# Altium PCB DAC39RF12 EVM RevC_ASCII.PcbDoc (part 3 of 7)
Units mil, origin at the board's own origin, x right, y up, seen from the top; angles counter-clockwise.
Board outline 5071.81 x 2716.54 mil, 16 copper layers (Top Layer, L2 GND1, L3 PWR1, L4 GND2, L5 PWR2, L6 GND3, L7 Ctrl Signal 1, L8 GND4, L9 GND5, L10 Ctrl Signal 2, L11 GND6, L12 PWR3, L13 GND7, L14 PWR4, L15 GND8, Bottom Layer), stack 82.4 mil thick; 596 components, 375 nets, 3310 pads, 1662 vias.
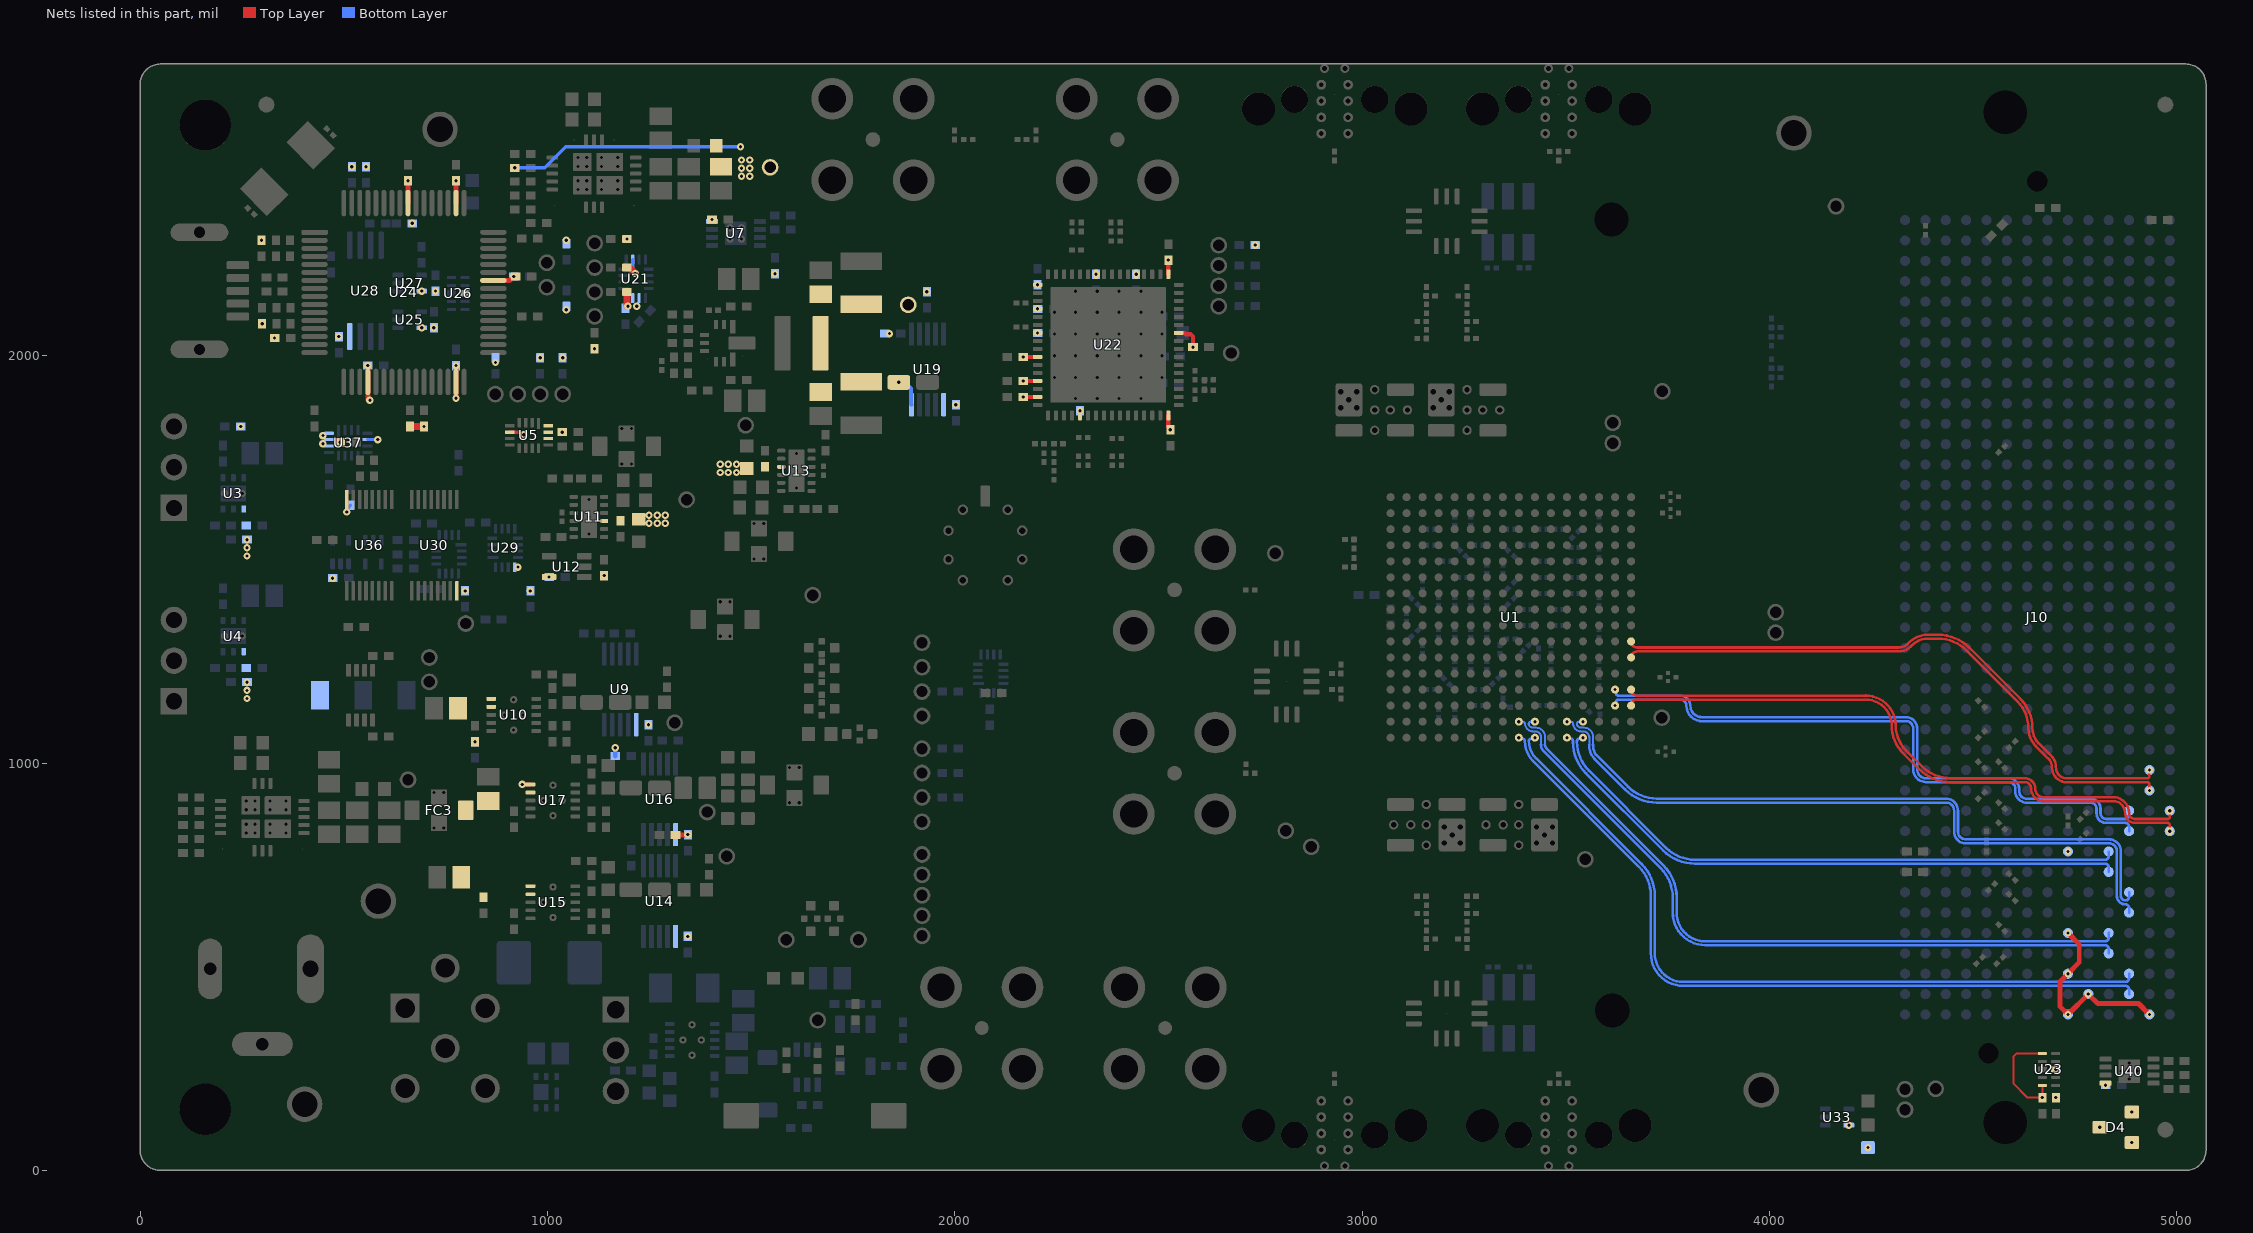
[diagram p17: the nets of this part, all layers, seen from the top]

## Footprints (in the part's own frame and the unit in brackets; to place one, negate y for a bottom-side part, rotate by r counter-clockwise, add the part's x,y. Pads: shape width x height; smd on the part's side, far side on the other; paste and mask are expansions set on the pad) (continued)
NKD0064A [mm] "QFN, 64-Leads, Body 9x9mm, Pitch 0.5mm"
  rrect40% 0.6x0.25 smd mask+0: 1(-4.4,3.75) 2(-4.4,3.25) 3(-4.4,2.75) 4(-4.4,2.25) 5(-4.4,1.75) 6(-4.4,1.25) 7(-4.4,0.75) 8(-4.4,0.25) 9(-4.4,-0.25) 10(-4.4,-0.75) 11(-4.4,-1.25) 12(-4.4,-1.75) 13(-4.4,-2.25) 14(-4.4,-2.75) 15(-4.4,-3.25) 16(-4.4,-3.75) 33(4.4,-3.75) 34(4.4,-3.25) 35(4.4,-2.75) 36(4.4,-2.25) 37(4.4,-1.75) 38(4.4,-1.25) 39(4.4,-0.75) 40(4.4,-0.25) 41(4.4,0.25) 42(4.4,0.75) 43(4.4,1.25) 44(4.4,1.75) 45(4.4,2.25) 46(4.4,2.75) 47(4.4,3.25) 48(4.4,3.75)
  rrect40% 0.25x0.6 smd mask+0: 17(-3.75,-4.4) 18(-3.25,-4.4) 19(-2.75,-4.4) 20(-2.25,-4.4) 21(-1.75,-4.4) 22(-1.25,-4.4) 23(-0.75,-4.4) 24(-0.25,-4.4) 25(0.25,-4.4) 26(0.75,-4.4) 27(1.25,-4.4) 28(1.75,-4.4) 29(2.25,-4.4) 30(2.75,-4.4) 31(3.25,-4.4) 32(3.75,-4.4) 49(3.75,4.4) 50(3.25,4.4) 51(2.75,4.4) 52(2.25,4.4) 53(1.75,4.4) 54(1.25,4.4) 55(0.75,4.4) 56(0.25,4.4) 57(-0.25,4.4) 58(-0.75,4.4) 59(-1.25,4.4) 60(-1.75,4.4) 61(-2.25,4.4) 62(-2.75,4.4) 63(-3.25,4.4) 64(-3.75,4.4)
  round 0.454 hole 0.2 mask+0: 65(-3.35,-2.04) 65(-3.35,-0.68) 65(-3.35,0.68) 65(-3.35,2.04) 65(-2.04,2.04) 65(-2.04,3.35) 65(-2.04,-0.68) 65(-2.04,0.68) 65(-2.04,-3.35) 65(-2.04,-2.04) 65(-0.68,3.35) 65(-0.68,2.04) 65(-0.68,0.68) 65(-0.68,-0.68) 65(-0.68,-2.04) 65(-0.68,-3.35) 65(0.68,3.35) 65(0.68,2.04) 65(0.68,0.68) 65(0.68,-0.68) 65(0.68,-2.04) 65(0.68,-3.35) 65(2.04,2.04) 65(2.04,3.35) 65(2.04,-0.68) 65(2.04,0.68) 65(2.04,-3.35) 65(2.04,-2.04) 65(3.35,-2.04) 65(3.35,-0.68) 65(3.35,0.68) 65(3.35,2.04)
  rrect1% 7.2x7.2 smd paste-3.6 mask+0: 65(0,0)
  silkscreen extent -4.65,-4.65 4.65,4.65
ProbePoint_TH_40mil [mil]
  round 41 hole 28: 1(0,0)
RAPC722X [mm] "Conn_DC Jack"
  oval 1.7x4.3 hole 1.01 slot 3.56 at 90 deg: 1(14.194,0)
  oval 1.5x3.8 hole 0.76 slot 3.05 at 90 deg: 2(7.946,0)
  oval 3.8x1.5 hole 0.76 slot 3.05 at 0 deg: 3(11.197,-4.7)
  silkscreen extent 0.2,-4.57 14.93,4.57
RDU0028A [mm]
  rrect40% 0.7x0.25 smd paste+0 mask+0: 3(-2.1,0.5) 4(-2.1,0) 5(-2.1,-0.5) 15(2.1,-0.5) 16(2.1,0) 17(2.1,0.5)
  rrect40% 0.25x0.7 smd paste+0 mask+0: 8(-1,-2.6) 9(-0.5,-2.6) 10(0,-2.6) 11(0.5,-2.6) 12(1,-2.6) 20(1,2.6) 21(0.5,2.6) 22(0,2.6) 23(-0.5,2.6) 24(-1,2.6)
  round 0.454 hole 0.2 mask+0: 25(-1,1) 25(-1,0.45) 25(-0.45,1) 25(-0.45,0.45) 26(-1,-0.475) 26(-1,-1.475) 26(-0.45,-0.475) 26(-0.45,-1.475) 27(0.45,-0.475) 27(0.45,-1.475) 27(1,-0.475) 27(1,-1.475) 28(0.45,1) 28(0.45,0.45) 28(1,1) 28(1,0.45)
  rrect9% 1.15x1.15 smd paste-1000 mask+0: 25(-0.725,0.725) 28(0.725,0.725)
  rrect9% 1.15x1.65 smd paste-1000 mask+0: 26(-0.725,-0.975) 27(0.725,-0.975)
  round 0.025 smd paste+0 mask+0.05: " "(-2.1,1.25) " "(-2.1,-1.25) " "(-1.987,-2.488) " "(-1.987,2.487) " "(1.987,-2.488) " "(1.988,2.488) " "(2.1,-1.25) " "(2.1,1.25)
  silkscreen extent -3.2,-3.13 2.63,3.13
RPY0014A [mm]
  rrect20% 0.575x0.25 smd paste+0 mask+0: 2(-1.412,0.5) 3(-1.412,0) 4(-1.412,-0.5)
  rrect20% 0.25x0.575 smd paste+0 mask+0: 6(-0.7,-1.162) 7(-0.2,-1.162) 13(-0.2,1.162) 14(-0.7,1.162)
  rrect10% 0.35x0.851 smd paste+0 mask+0: 8(0.35,-1.025) 12(0.35,1.025)
  rrect10% 1.675x0.8 smd paste-0.825 mask+0: 10(0.913,0)
  round 0.025 smd paste+0 mask+0.05: " "(-1.213,0.987) " "(-1.212,-0.988) " "(0.975,-0.8) " "(0.975,0.8)
  silkscreen extent -2.4,-1.63 1.92,1.63
RSV0016A [mm] "QFN, 16-Leads, Body 1.8x2.6mm, Pitch 0.4mm, TI Recommended"
  rrect25% 0.7x0.2 smd mask+0: 1(-0.75,0.6)
  rrect25% 0.6x0.2 smd mask+0: 2(-0.8,0.2) 3(-0.8,-0.2) 4(-0.8,-0.6) 9(0.8,-0.6) 10(0.8,-0.2) 11(0.8,0.2) 12(0.8,0.6)
  rrect25% 0.2x0.6 smd mask+0: 5(-0.6,-1.2) 6(-0.2,-1.2) 7(0.2,-1.2) 8(0.6,-1.2) 13(0.6,1.2) 14(0.2,1.2) 15(-0.2,1.2) 16(-0.6,1.2)
  silkscreen extent -1.08,-1.33 1.08,1.45
Samtec_ASP-184330-01 [mil] "Terminal Array, 1.27mm, 40x14, SMT"
  round 25 smd far side paste-25.2: A1(975,-225) A2(925,-225) A3(875,-225) A4(825,-225) A5(775,-225) A6(725,-225) A7(675,-225) A8(625,-225) A9(575,-225) A10(525,-225) A11(475,-225) A12(425,-225) A13(375,-225) A14(325,-225) A15(275,-225) A16(225,-225) A17(175,-225) A18(125,-225) A19(75,-225) A20(25,-225) A21(-25,-225) A22(-75,-225) A23(-125,-225) A24(-175,-225) A25(-225,-225) A26(-275,-225) A27(-325,-225) A28(-375,-225) A29(-425,-225) A30(-475,-225) A31(-525,-225) A32(-575,-225) A33(-625,-225) A34(-675,-225) A35(-725,-225) A36(-775,-225) A37(-825,-225) A38(-875,-225) A39(-925,-225) A40(-975,-225) B1(975,-175) B2(925,-175) B3(875,-175) B4(825,-175) B5(775,-175) B6(725,-175) B7(675,-175) B8(625,-175) B9(575,-175) B10(525,-175) B11(475,-175) B12(425,-175) B13(375,-175) B14(325,-175) B15(275,-175) B16(225,-175) B17(175,-175) B18(125,-175) B19(75,-175) B20(25,-175) B21(-25,-175) B22(-75,-175) B23(-125,-175) B24(-175,-175) B25(-225,-175) B26(-275,-175) B27(-325,-175) B28(-375,-175) B29(-425,-175) B30(-475,-175) B31(-525,-175) B32(-575,-175) B33(-625,-175) B34(-675,-175) B35(-725,-175) B36(-775,-175) B37(-825,-175) B38(-875,-175) B39(-925,-175) B40(-975,-175) C1(975,-125) C2(925,-125) C3(875,-125) C4(825,-125) C5(775,-125) C6(725,-125) C7(675,-125) C8(625,-125) C9(575,-125) C10(525,-125) C11(475,-125) C12(425,-125) C13(375,-125) C14(325,-125) C15(275,-125) C16(225,-125) C17(175,-125) C18(125,-125) C19(75,-125) C20(25,-125) C21(-25,-125) C22(-75,-125) C23(-125,-125) C24(-175,-125) C25(-225,-125) C26(-275,-125) C27(-325,-125) C28(-375,-125) C29(-425,-125) C30(-475,-125) C31(-525,-125) C32(-575,-125) C33(-625,-125) C34(-675,-125) C35(-725,-125) C36(-775,-125) C37(-825,-125) C38(-875,-125) C39(-925,-125) C40(-975,-125) D1(975,-75) D2(925,-75) D3(875,-75) D4(825,-75) D5(775,-75) D6(725,-75) D7(675,-75) D8(625,-75) D9(575,-75) D10(525,-75) D11(475,-75) D12(425,-75) D13(375,-75) D14(325,-75) D15(275,-75) D16(225,-75) D17(175,-75) D18(125,-75) D19(75,-75) D20(25,-75) D21(-25,-75) D22(-75,-75) D23(-125,-75) D24(-175,-75) D25(-225,-75) D26(-275,-75) D27(-325,-75) D28(-375,-75) D29(-425,-75) D30(-475,-75) D31(-525,-75) D32(-575,-75) D33(-625,-75) D34(-675,-75) D35(-725,-75) D36(-775,-75) D37(-825,-75) D38(-875,-75) D39(-925,-75) D40(-975,-75) E1(975,-25) E2(925,-25) E3(875,-25) E4(825,-25) E5(775,-25) E6(725,-25) E7(675,-25) E8(625,-25) E9(575,-25) E10(525,-25) E11(475,-25) E12(425,-25) E13(375,-25) E14(325,-25) E15(275,-25) E16(225,-25) E17(175,-25) E18(125,-25) E19(75,-25) E20(25,-25) E21(-25,-25) E22(-75,-25) E23(-125,-25) E24(-175,-25) E25(-225,-25) E26(-275,-25) E27(-325,-25) E28(-375,-25) E29(-425,-25) E30(-475,-25) E31(-525,-25) E32(-575,-25) E33(-625,-25) E34(-675,-25) E35(-725,-25) E36(-775,-25) E37(-825,-25) E38(-875,-25) E39(-925,-25) E40(-975,-25) F1(975,25) F2(925,25) F3(875,25) F4(825,25) F5(775,25) F6(725,25) F7(675,25) F8(625,25) F9(575,25) F10(525,25) F11(475,25) F12(425,25) F13(375,25) F14(325,25) F15(275,25) F16(225,25) F17(175,25) F18(125,25) F19(75,25) F20(25,25) F21(-25,25) F22(-75,25) F23(-125,25) F24(-175,25) F25(-225,25) F26(-275,25) F27(-325,25) F28(-375,25) F29(-425,25) F30(-475,25) F31(-525,25) F32(-575,25) F33(-625,25) F34(-675,25) F35(-725,25) F36(-775,25) F37(-825,25) F38(-875,25) F39(-925,25) F40(-975,25) G1(975,75) G2(925,75) G3(875,75) G4(825,75) G5(775,75) G6(725,75) G7(675,75) G8(625,75) G9(575,75) G10(525,75) G11(475,75) G12(425,75) G13(375,75) G14(325,75) G15(275,75) G16(225,75) G17(175,75) G18(125,75) G19(75,75) G20(25,75) G21(-25,75) G22(-75,75) G23(-125,75) G24(-175,75) G25(-225,75) G26(-275,75) G27(-325,75) G28(-375,75) G29(-425,75) G30(-475,75) G31(-525,75) G32(-575,75) G33(-625,75) G34(-675,75) G35(-725,75) G36(-775,75) G37(-825,75) G38(-875,75) G39(-925,75) G40(-975,75) H1(975,125) H2(925,125) H3(875,125) H4(825,125) H5(775,125) H6(725,125) H7(675,125) H8(625,125) H9(575,125) H10(525,125) H11(475,125) H12(425,125) H13(375,125) H14(325,125) H15(275,125) H16(225,125) H17(175,125) H18(125,125) H19(75,125) H20(25,125) H21(-25,125) H22(-75,125) H23(-125,125) H24(-175,125) H25(-225,125) H26(-275,125) H27(-325,125) H28(-375,125) H29(-425,125) H30(-475,125) H31(-525,125) H32(-575,125) H33(-625,125) H34(-675,125) H35(-725,125) H36(-775,125) H37(-825,125) H38(-875,125) H39(-925,125) H40(-975,125) J1(975,175) J2(925,175) J3(875,175) J4(825,175) J5(775,175) J6(725,175) J7(675,175) J8(625,175) J9(575,175) J10(525,175) J11(475,175) J12(425,175) J13(375,175) J14(325,175) J15(275,175) J16(225,175) J17(175,175) J18(125,175) J19(75,175) J20(25,175) J21(-25,175) J22(-75,175) J23(-125,175) J24(-175,175) J25(-225,175) J26(-275,175) J27(-325,175) J28(-375,175) J29(-425,175) J30(-475,175) J31(-525,175) J32(-575,175) J33(-625,175) J34(-675,175) J35(-725,175) J36(-775,175) J37(-825,175) J38(-875,175) J39(-925,175) J40(-975,175) K1(975,225) K2(925,225) K3(875,225) K4(825,225) K5(775,225) K6(725,225) K7(675,225) K8(625,225) K9(575,225) K10(525,225) K11(475,225) K12(425,225) K13(375,225) K14(325,225) K15(275,225) K16(225,225) K17(175,225) K18(125,225) K19(75,225) K20(25,225) K21(-25,225) K22(-75,225) K23(-125,225) K24(-175,225) K25(-225,225) K26(-275,225) K27(-325,225) K28(-375,225) K29(-425,225) K30(-475,225) K31(-525,225) K32(-575,225) K33(-625,225) K34(-675,225) K35(-725,225) K36(-775,225) K37(-825,225) K38(-875,225) K39(-925,225) K40(-975,225) L1(975,275) L2(925,275) L3(875,275) L4(825,275) L5(775,275) L6(725,275) L7(675,275) L8(625,275) L9(575,275) L10(525,275) L11(475,275) L12(425,275) L13(375,275) L14(325,275) L15(275,275) L16(225,275) L17(175,275) L18(125,275) L19(75,275) L20(25,275) L21(-25,275) L22(-75,275) L23(-125,275) L24(-175,275) L25(-225,275) L26(-275,275) L27(-325,275) L28(-375,275) L29(-425,275) L30(-475,275) L31(-525,275) L32(-575,275) L33(-625,275) L34(-675,275) L35(-725,275) L36(-775,275) L37(-825,275) L38(-875,275) L39(-925,275) L40(-975,275) M1(975,325) M2(925,325) M3(875,325) M4(825,325) M5(775,325) M6(725,325) M7(675,325) M8(625,325) M9(575,325) M10(525,325) M11(475,325) M12(425,325) M13(375,325) M14(325,325) M15(275,325) M16(225,325) M17(175,325) M18(125,325) M19(75,325) M20(25,325) M21(-25,325) M22(-75,325) M23(-125,325) M24(-175,325) M25(-225,325) M26(-275,325) M27(-325,325) M28(-375,325) M29(-425,325) M30(-475,325) M31(-525,325) M32(-575,325) M33(-625,325) M34(-675,325) M35(-725,325) M36(-775,325) M37(-825,325) M38(-875,325) M39(-925,325) M40(-975,325) Y1(975,-325) Y2(925,-325) Y3(875,-325) Y4(825,-325) Y5(775,-325) Y6(725,-325) Y7(675,-325) Y8(625,-325) Y9(575,-325) Y10(525,-325) Y11(475,-325) Y12(425,-325) Y13(375,-325) Y14(325,-325) Y15(275,-325) Y16(225,-325) Y17(175,-325) Y18(125,-325) Y19(75,-325) Y20(25,-325) Y21(-25,-325) Y22(-75,-325) Y23(-125,-325) Y24(-175,-325) Y25(-225,-325) Y26(-275,-325) Y27(-325,-325) Y28(-375,-325) Y29(-425,-325) Y30(-475,-325) Y31(-525,-325) Y32(-575,-325) Y33(-625,-325) Y34(-675,-325) Y35(-725,-325) Y36(-775,-325) Y37(-825,-325) Y38(-875,-325) Y39(-925,-325) Y40(-975,-325) Z1(975,-275) Z2(925,-275) Z3(875,-275) Z4(825,-275) Z5(775,-275) Z6(725,-275) Z7(675,-275) Z8(625,-275) Z9(575,-275) Z10(525,-275) Z11(475,-275) Z12(425,-275) Z13(375,-275) Z14(325,-275) Z15(275,-275) Z16(225,-275) Z17(175,-275) Z18(125,-275) Z19(75,-275) Z20(25,-275) Z21(-25,-275) Z22(-75,-275) Z23(-125,-275) Z24(-175,-275) Z25(-225,-275) Z26(-275,-275) Z27(-325,-275) Z28(-375,-275) Z29(-425,-275) Z30(-475,-275) Z31(-525,-275) Z32(-575,-275) Z33(-625,-275) Z34(-675,-275) Z35(-725,-275) Z36(-775,-275) Z37(-825,-275) Z38(-875,-275) Z39(-925,-275) Z40(-975,-275)
  round 0 hole 105.91 unplated: ""(-1240,79) ""(1240,79)
  round 0 hole 50 unplated: ""(-1070.5,120) ""(1070.5,0)
  round 35 on Bottom Paste: ""(-975,-325) ""(-975,-275) ""(-975,-225) ""(-975,-175) ""(-975,-125) ""(-975,-75) ""(-975,-25) ""(-975,25) ""(-975,75) ""(-975,125) ""(-975,175) ""(-975,225) ""(-975,275) ""(-975,325) ""(-925,-325) ""(-925,-275) ""(-925,-225) ""(-925,-175) ""(-925,-125) ""(-925,-75) ""(-925,-25) ""(-925,25) ""(-925,75) ""(-925,125) ""(-925,175) ""(-925,225) ""(-925,275) ""(-925,325) ""(-875,-325) ""(-875,-275) ""(-875,-225) ""(-875,-175) ""(-875,-125) ""(-875,-75) ""(-875,-25) ""(-875,25) ""(-875,75) ""(-875,125) ""(-875,175) ""(-875,225) ""(-875,275) ""(-875,325) ""(-825,-325) ""(-825,-275) ""(-825,-225) ""(-825,-175) ""(-825,-125) ""(-825,-75) ""(-825,-25) ""(-825,25) ""(-825,75) ""(-825,125) ""(-825,175) ""(-825,225) ""(-825,275) ""(-825,325) ""(-775,-325) ""(-775,-275) ""(-775,-225) ""(-775,-175) ""(-775,-125) ""(-775,-75) ""(-775,-25) ""(-775,25) ""(-775,75) ""(-775,125) ""(-775,175) ""(-775,225) ""(-775,275) ""(-775,325) ""(-725,-325) ""(-725,-275) ""(-725,-225) ""(-725,-175) ""(-725,-125) ""(-725,-75) ""(-725,-25) ""(-725,25) ""(-725,75) ""(-725,125) ""(-725,175) ""(-725,225) ""(-725,275) ""(-725,325) ""(-675,-325) ""(-675,-275) ""(-675,-225) ""(-675,-175) ""(-675,-125) ""(-675,-75) ""(-675,-25) ""(-675,25) ""(-675,75) ""(-675,125) ""(-675,175) ""(-675,225) ""(-675,275) ""(-675,325) ""(-625,-325) ""(-625,-275) ""(-625,-225) ""(-625,-175) ""(-625,-125) ""(-625,-75) ""(-625,-25) ""(-625,25) ""(-625,75) ""(-625,125) ""(-625,175) ""(-625,225) ""(-625,275) ""(-625,325) ""(-575,-325) ""(-575,-275) ""(-575,-225) ""(-575,-175) ""(-575,-125) ""(-575,-75) ""(-575,-25) ""(-575,25) ""(-575,75) ""(-575,125) ""(-575,175) ""(-575,225) ""(-575,275) ""(-575,325) ""(-525,-325) ""(-525,-275) ""(-525,-225) ""(-525,-175) ""(-525,-125) ""(-525,-75) ""(-525,-25) ""(-525,25) ""(-525,75) ""(-525,125) ""(-525,175) ""(-525,225) ""(-525,275) ""(-525,325) ""(-475,-325) ""(-475,-275) ""(-475,-225) ""(-475,-175) ""(-475,-125) ""(-475,-75) ""(-475,-25) ""(-475,25) ""(-475,75) ""(-475,125) ""(-475,175) ""(-475,225) ""(-475,275) ""(-475,325) ""(-425,-325) ""(-425,-275) ""(-425,-225) ""(-425,-175) ""(-425,-125) ""(-425,-75) ""(-425,-25) ""(-425,25) ""(-425,75) ""(-425,125) ""(-425,175) ""(-425,225) ""(-425,275) ""(-425,325) ""(-375,-325) ""(-375,-275) ""(-375,-225) ""(-375,-175) ""(-375,-125) ""(-375,-75) ""(-375,-25) ""(-375,25) ""(-375,75) ""(-375,125) ""(-375,175) ""(-375,225) ""(-375,275) ""(-375,325) ""(-325,-325) ""(-325,-275) ""(-325,-225) ""(-325,-175) ""(-325,-125) ""(-325,-75) ""(-325,-25) ""(-325,25) ""(-325,75) ""(-325,125) ""(-325,175) ""(-325,225) ""(-325,275) ""(-325,325) ""(-275,-325) ""(-275,-275) ""(-275,-225) ""(-275,-175) ""(-275,-125) ""(-275,-75) ""(-275,-25) ""(-275,25) ""(-275,75) ""(-275,125) ""(-275,175) ""(-275,225) ""(-275,275) ""(-275,325) ""(-225,275) ""(-225,325) ""(-225,-225) ""(-225,-175) ""(-225,-125) ""(-225,-75) ""(-225,-25) ""(-225,25) ""(-225,75) ""(-225,125) ""(-225,175) ""(-225,225) ""(-225,-325) ""(-225,-275) ""(-175,275) ""(-175,325) ""(-175,-225) ""(-175,-175) ""(-175,-125) ""(-175,-75) ""(-175,-25) ""(-175,25) ""(-175,75) ""(-175,125) ""(-175,175) ""(-175,225) ""(-175,-325) ""(-175,-275) ""(-125,125) ""(-125,175) ""(-125,225) ""(-125,275) ""(-125,325) ""(-125,-75) ""(-125,-25) ""(-125,25) ""(-125,75) ""(-125,-325) ""(-125,-275) ""(-125,-225) ""(-125,-175) ""(-125,-125) ""(-75,125) ""(-75,175) ""(-75,225) ""(-75,275) ""(-75,325) ""(-75,-75) ""(-75,-25) ""(-75,25) ""(-75,75) ""(-75,-325) ""(-75,-275) ""(-75,-225) ""(-75,-175) ""(-75,-125) ""(-25,325) ""(-25,275) ""(-25,225) ""(-25,175) ""(-25,125) ""(-25,75) ""(-25,-25) ""(-25,25) ""(-25,-75) ""(-25,-125) ""(-25,-175) ""(-25,-225) ""(-25,-275) ""(-25,-325) ""(25,325) ""(25,275) ""(25,225) ""(25,175) ""(25,125) ""(25,75) ""(25,-25) ""(25,25) ""(25,-75) ""(25,-125) ""(25,-175) ""(25,-225) ""(25,-275) ""(25,-325) ""(75,125) ""(75,175) ""(75,225) ""(75,275) ""(75,325) ""(75,-75) ""(75,-25) ""(75,25) ""(75,75) ""(75,-325) ""(75,-275) ""(75,-225) ""(75,-175) ""(75,-125) ""(125,125) ""(125,175) ""(125,225) ""(125,275) ""(125,325) ""(125,-75) ""(125,-25) ""(125,25) ""(125,75) ""(125,-325) ""(125,-275) ""(125,-225) ""(125,-175) ""(125,-125) ""(175,275) ""(175,325) ""(175,-225) ""(175,-175) ""(175,-125) ""(175,-75) ""(175,-25) ""(175,25) ""(175,75) ""(175,125) ""(175,175) ""(175,225) ""(175,-325) ""(175,-275) ""(225,275) ""(225,325) ""(225,-225) ""(225,-175) ""(225,-125) ""(225,-75) ""(225,-25) ""(225,25) ""(225,75) ""(225,125) ""(225,175) ""(225,225) ""(225,-325) ""(225,-275) ""(275,-325) ""(275,-275) ""(275,-225) ""(275,-175) ""(275,-125) ""(275,-75) ""(275,-25) ""(275,25) ""(275,75) ""(275,125) ""(275,175) ""(275,225) ""(275,275) ""(275,325) ""(325,-325) ""(325,-275) ""(325,-225) ""(325,-175) ""(325,-125) ""(325,-75) ""(325,-25) ""(325,25) ""(325,75) ""(325,125) ""(325,175) ""(325,225) ""(325,275) ""(325,325) ""(375,-325) ""(375,-275) ""(375,-225) ""(375,-175) ""(375,-125) ""(375,-75) ""(375,-25) ""(375,25) ""(375,75) ""(375,125) ""(375,175) ""(375,225) ""(375,275) ""(375,325) ""(425,-325) ""(425,-275) ""(425,-225) ""(425,-175) ""(425,-125) ""(425,-75) ""(425,-25) ""(425,25) ""(425,75) ""(425,125) ""(425,175) ""(425,225) ""(425,275) ""(425,325) ""(475,-325) ""(475,-275) ""(475,-225) ""(475,-175) ""(475,-125) ""(475,-75) ""(475,-25) ""(475,25) ""(475,75) ""(475,125) ""(475,175) ""(475,225) ""(475,275) ""(475,325) ""(525,-325) ""(525,-275) ""(525,-225) ""(525,-175) ""(525,-125) ""(525,-75) ""(525,-25) ""(525,25) ""(525,75) ""(525,125) ""(525,175) ""(525,225) ""(525,275) ""(525,325) ""(575,-325) ""(575,-275) ""(575,-225) ""(575,-175) ""(575,-125) ""(575,-75) ""(575,-25) ""(575,25) ""(575,75) ""(575,125) ""(575,175) ""(575,225) ""(575,275) ""(575,325) ""(625,-325) ""(625,-275) ""(625,-225) ""(625,-175) ""(625,-125) ""(625,-75) ""(625,-25) ""(625,25) ""(625,75) ""(625,125) ""(625,175) ""(625,225) ""(625,275) ""(625,325) ""(675,-325) ""(675,-275) ""(675,-225) ""(675,-175) ""(675,-125) ""(675,-75) ""(675,-25) ""(675,25) ""(675,75) ""(675,125) ""(675,175) ""(675,225) ""(675,275) ""(675,325) ""(725,-325) ""(725,-275) ""(725,-225) ""(725,-175) ""(725,-125) ""(725,-75) ""(725,-25) ""(725,25) ""(725,75) ""(725,125) ""(725,175) ""(725,225) ""(725,275) ""(725,325) ""(775,-325) ""(775,-275) ""(775,-225) ""(775,-175) ""(775,-125) ""(775,-75) ""(775,-25) ""(775,25) ""(775,75) ""(775,125) ""(775,175) ""(775,225) ""(775,275) ""(775,325) ""(825,-325) ""(825,-275) ""(825,-225) ""(825,-175) ""(825,-125) ""(825,-75) ""(825,-25) ""(825,25) ""(825,75) ""(825,125) ""(825,175) ""(825,225) ""(825,275) ""(825,325) ""(875,-325) ""(875,-275) ""(875,-225) ""(875,-175) ""(875,-125) ""(875,-75) ""(875,-25) ""(875,25) ""(875,75) ""(875,125) ""(875,175) ""(875,225) ""(875,275) ""(875,325) ""(925,-325) ""(925,-275) ""(925,-225) ""(925,-175) ""(925,-125) ""(925,-75) ""(925,-25) ""(925,25) ""(925,75) ""(925,125) ""(925,175) ""(925,225) ""(925,275) ""(925,325) ""(975,-325) ""(975,-275) ""(975,-225) ""(975,-175) ""(975,-125) ""(975,-75) ""(975,-25) ""(975,25) ""(975,75) ""(975,125) ""(975,175) ""(975,225) ""(975,275) ""(975,325)
SF-1206F500M-2_1206 [mm]
  rrect7% 1.45x1.8 smd paste+0 mask+0: 1(-1.475,0) 2(1.475,0)
  silkscreen extent -0.55,-0.9 0.55,0.9
SMBJ15CA [mil]
  rrect20% 85x107.99 smd: 1(-87.01,0) 2(87.01,0)
  silkscreen extent -125,-79 125,79
SOD-123 [mm] "On Semi recommended land pattern"
  rrect20% 0.915x1.22 smd: 1(-1.637,0) 2(1.637,0)
  silkscreen extent -2.74,-1.17 2.03,1.17
SOT-323-DIO [mm]
  rrect21% 0.9x0.8 smd: 1(-1,0.95) 2(-1,-0.95) 3(1,0)
  silkscreen extent -1.14,-1.52 0.77,1.52
TCBT123 [mm]
  rrect30% 0.79x1.68 smd: 1(-1.27,-1.61) 2(1.27,-1.61) 4(-1.27,1.61)
  round 0.584 hole 0.33 mask+0: 3(0.135,1.11) 3(0.135,2.11) 3(0.635,1.61) 3(1.135,2.11) 3(1.135,1.11) 5(-1.27,0) 5(0,0) 5(0,-2.04) 5(0,-0.97) 5(1.27,0)
  rrect20% 2.06x1.68 smd: 3(0.635,1.61)
  round 0.025 smd paste+0 mask+0.1: " "(0,-1.052)
  silkscreen extent -1.91,-2.9 1.91,1.9
TDFN8#1 [mm]
  rrect30% 0.75x0.3 smd paste+0 mask+0: 1(-1.5,0.75) 2(-1.5,0.25) 3(-1.5,-0.25) 4(-1.5,-0.75) 5(1.478,-0.75) 6(1.478,-0.25) 7(1.478,0.25) 8(1.478,0.75)
  round 0.327 / inner round 0.454 / far side round 0.454 hole 0.2 mask+0: 9(-0.354,-0.354) 9(-0.354,0.354) 9(0.354,-0.354) 9(0.354,0.354)
  rrect10% 1.36x1.46 smd paste+0 mask+0: 9(0,0)
  silkscreen extent -2.23,0.67 -2.14,0.83
TDFN8#2 [mm]
  rrect30% 0.75x0.3 smd paste+0 mask+0: 1(-1.5,0.75) 2(-1.5,0.25) 3(-1.5,-0.25) 4(-1.5,-0.75) 5(1.478,-0.75) 6(1.478,-0.25) 7(1.478,0.25) 8(1.478,0.75)
  round 0.327 / inner round 0.454 / far side round 0.454 hole 0.2 mask+0: 9(-0.5,0) 9(0,0.5) 9(0,0) 9(0,-0.5) 9(0.5,0)
  rrect10% 1.36x1.46 smd paste+0 mask+0: 9(0,0)
  silkscreen extent -2.23,0.67 -2.14,0.83
TI_Stacked_Overlay_Small [mil]
TSSOP-8 [mm] "TSSOP, 8-Leads, Body 3.1x4.5mm (max), Pitch 0.65mm, IPC Medium Density"
  rrect50% 1.7x0.35 smd: 1(-2.85,0.975) 2(-2.85,0.325) 3(-2.85,-0.325) 4(-2.85,-0.975) 5(2.85,-0.975) 6(2.85,-0.325) 7(2.85,0.325) 8(2.85,0.975)
  silkscreen extent -2.97,-1.55 1.6,1.82
WEEE_Minimum [mil] "WEEElie bin"
  silkscreen extent 22,-71 54,74
XGL4020 [mm]
  rrect10% 0.98x3.4 smd paste+0 mask+0: 1(-1.185,0) 2(1.185,0)
  silkscreen extent -2.67,-2.15 2.15,2.15
XTAL_ABM3 [mm] "Abracon recommended land pattern 12.28.10"
  rect 1.9x2.4 smd: 1(-2.05,0) 2(2.05,0)
  silkscreen extent -2.67,-1.78 2.67,1.78

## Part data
C1 C2 C3 C4 C5 C6 C17 C22 C52 C60 C61 C62 C99 C100 C101 C102 C103 C104 C105: library part 0201RFCaps0693, "Broadband Capacitors"
C7 C8 C9: library part capcc02687, "CAP CER 1UF 50V X7R 0805"
C10 C11: library part capcc03751, "CAP CER 1000PF 50V X7R 0603"
C12 C14 C86 C87: library part capcc03515, "CAP CER 10UF 25V X5R 0805"
C13 C15 C49 C79 C85: library part capcc03139, "CAP CER 4.7UF 10V X5R 0402"
C16 C18 C21 C28: library part 0201RFCaps0050, "CAP CER 0.5PF 50V C0G/NP0 0201"
C19 C29 C30 C33: library part capcc09400, "CAP CER 10UF 25V X5R 0603"
C20 C34 C42 C55 C68 C69 C70 C72 C73 C80 C84 C95 C97 C98 C108 C115 C116 C117 C118 C119 C120 C121 C122 C123 C124 C125 C126 C145 C155 C161 C162 C163 C164 C165 C167 C168 C169 C170 C171 C245: library part CMP-0006607-2, "CAP, CERM, 0.1 uF, 25 V, +/- 10%, X5R, 0402"
C23 C24 C25 C26 C35 C36 C37 C38 C40 C47 C50 C91 C92: library part capcc09395, "CAP CER 22UF 10V X7S 0805"
C27 C41: library part capcc01693, "CAP CER 0.22UF 16V X5R 0402"
C31 C32 C77 C81 C90 C106 C107 C127 C128 C131 C132 C133 C134 C137 C138 C139 C140 C172 C173 C174 C175 C176 C177 C178 C179 C180 C181 C182 C183 C184 C185 C186 C187 C188 C189 C190 C191 C192 C193 C194 C195 C196 C197 C198 C199 C200 C201 C202 C203 C204 C205 C206 C207 C208 C209 C210 C211 C212 C213 C214 C215 C216 C217 C218 C219 C220 C221 C222 C223 C224 C225 C226 C227 C228 C229 C230 C231 C232 C233 C234 C239 C240 C241 C242 C243 C244: library part capcc09263, "CAP CER 0.1UF 16V X7R 0201"
C39: library part capcc03130, "CAP CER 3.3UF 10V X5R 0603"
C43: library part capcc08380, "CAP CER 82PF 50V C0G/NP0 0201"
C44 C48 C51 C53 C54 C74 C78: library part dcp00009, "CAP FEEDTHRU 1UF 20% 6.3V 0603"
C45 C56 C59 C63 C64 C67 C71 C75 C82: library part capcc03657, "CAP CER 10UF 10V X5R 0603"
C46 C76: library part capcc02750, "CAP CER 1UF 25V X5R 0402"
C57 C65 C96: library part capcc03112, "CAP CER 2.2UF 10V X5R 0402"
C58 C66: library part capcc09264, "CAP CER 1UF 10V X5R 0201"
C83 C109 C110 C111: "CAP CER 47UF 6.3V X5R 0603"
C88 C89 C147 C148 C149 C150 C151 C152 C154 C158: library part capcc01256, "CAP CER 0.1UF 25V X5R 0402"
C93 C94: library part capcc03627, "CAP CER 47UF 16V X5R 1210"
C144: library part capcc03566, "CAP CER 10UF 10V X5R 0603"
C146 C153: library part capcc03076, "CAP CER 4.7UF 6.3V X5R 0402"
C159 C160: library part capcc08580, "CAP CER 18PF 25V C0H 0201"
C235 C236 C237 C238: library part dcp00005, "CAP FEEDTHRU 0.47UF 6.3V 0402"
D1: library part cmp00438, "DIODE SCHOTTKY 30V 1A SOD123"
D2: library part cmp00440, "24.4V Clamp 24.6A Ipp Tvs Diode"
D3 D5: library part cmp00247, "LED GREEN CLEAR CHIP SMD"
D4: "Diode Array 1 Pair Common Cathode 20 V 400mA (DC)"
F1: library part cmp00082, "FUSE BOARD MOUNT 2.5A 32VDC 1206"
F2: library part cmp00325, "EMI Filter Circuits 40 DB 50V 10A"
FB1 FB2 FB3 FB4 FB5: library part dcp00004, "8.5 Ohms @ 100 MHz 1 Power Line Ferrite Bead 0603 (1608 Metric) 8A 4mOhm"
FB6: library part dcp00579, "FERRITEBEAD SMD Z100MHZ=470OHM 2"
FB7 FB8: library part dcp00209, "0402 (1005) 150OHM (TYP.) 1000MA"
FC3 FC5 FC7 FC8 FC10: library part dcp00001, "Feed through capactior 27uF"
FID1 FID2 FID3: library part cmp00099, "Fiducial"
H3 H4: library part cmp00097, "Hex Standoff Threaded #4-40 Stainless Steel 1.250\" (31.75mm) 1 1/4"
J1 J2 J3 J4: library part cmp00522, "2.92mm Connector Receptacle, Female Socket 50 Ohms Board Edge, End Launch Compression"
J5: library part cmp00022, "Power Jack, mini, 2.1mm OD, R/A, TH"
J6 J11 J12 J13: "SMA Connector Jack, Female Socket 50Ohm Surface Mount, Through Hole Solder"
J7 J8: library part SMA, "SMA Connector Jack, Female Socket 50Ohm Surface Mount, Through Hole Solder"
J9: library part "USB 2p0", "Connector, Receptacle, Mini-USB Type B, R/A, SMT"
J10: library part asp-184330-01, "FMC+, High Density Array, Male / EVM Connector 40x14"
J14: library part cmp00032, "SMP Connector Plug, Male Pin 50Ohm Surface Mount Solder"
L1: library part LSMT56800072, "FIXED IND 1.5UH 11.1A 14.3 MOHM"
LBL1: library part cmp00106, "Thermal Transfer Printable Labels, 0.650\" W x 0.200\" H - 10,000 per roll"
Logo1: library part cmp00105, "FDL"
LOGO2: library part cmp00100, "IEC 61010-1 Hot Surface Warning"
Logo3: library part FCC_disclaimer, "FCC_disclaimer"
Logo4: library part cmp00317
Logo5: library part cmp00101
LOGO6: library part cmp00103, "CE_Mark"
Logo7: library part cmp00104, "Texas Instrument Corporate Signature"
MP1: library part cmp00111, "Heat Sink Passive BGA Straight Adhesive 9.3C/W Black Anodized"
MP5: library part cmp00110, "Fan Tubeaxial 5VDC Square - 17mm L x 17mm H Sleeve 0.636 CFM (0.018m³/min) 2 Wire Leads"
PP1 PP2: library part cmp00025, "Probe Point that can be used in lue of a test point"
PP3 PP4 PP5 PP6 PP7 PP8 PP9 PP10 PP11 PP12 PP13 PP14 PP15 PP16 PP17 PP18 PP19 PP20 PP21 PP22 PP23 PP24 PP25 PP26 PP27 PP28 PP29 PP30 PP31 PP32 PP33 PP34 PP35 PP36 PP37 PP38 PP39 PP40 PP41 PP42 PP43 PP44 PP45 PP46 PP47 PP48 PP49 PP50 PP51 PP52 PP53 PP54 PP55 PP56 PP57: "Probe Point that can be used in lue of a test point"
Q1: library part cmp00159, "MOSFET, N-CH, 20 V, 10 A"
R1 R2 R3 R4 R5 R6 R9 R10 R11 R12 R13 R14 R15 R16 R19 R20 R92 R93 R94 R96 R97 R98 R99 R100 R107 R108 R109 R110 R148 R152 R153 R154 R156 R158 R159 R160 R161 R162 R163 R164 R165 R166 R167 R168 R169 R171 R172 R176 R177 R178: library part RSMD020101699, "RES SMD 0 OHM JUMPER 1/20W 0201"
R7 R8 R17 R18: library part RSMD020100157, "RES SMD 140 OHM 1% 1/20W 0201"
R21: library part RSMD040200026, "RES SMD 1M OHM 1% 1/10W 0402"
R22: library part RSMD040202774, "RES SMD 45.3K OHM 1% 1/10W 0402"
R23: library part RSMD040200944, "RES SMD 162K OHM 1% 1/10W 0402"
R24: library part RSMD080501521, "RES SMD 4.87K OHM 1% 1/8W 0805"
R25 R26: library part RSMD120607282, "RES 0 OHM JUMPER 1206 SMD"
R27 R28 R30 R36 R40 R45 R46 R47 R58 R60 R63 R65 R70 R78 R83 R95 R111 R116 R118 R119 R120 R122 R131 R132 R133 R135 R138 R139 R140 R144 R157 R170 R173 R174 R175 R182 R183 R184 R185 R186 R187 R188 R189 R190 R192 R193: library part RSMD040200314, "RES SMD 10K OHM 1% 1/10W 0402"
R29: library part RSMD040201348, "RES 20K OHM 1% 1/10W 0402 SMD"
R31: library part RSMD040202356, "RES 36K OHM 1% 1/10W 0402 SMD"
R32 R33: library part RSMD040200519, "RES SMD 12K OHM 1% 1/10W 0402"
R34 R43 R91: library part RSMD020100177, "RES SMD 49.9 OHM 1% 1/20W 0201"
R35 R101 R102 R105 R106: library part RSMD020101357, "RES 560 OHM 5% 1/20W 0201 SMD"
R37 R38 R103 R104: library part RSMD020100105, "RES SMD 240 OHM 1% 1/20W 0201"
R39: library part RSMD040200803, "RES SMD 15.4KOHM 0.1% 1/16W 0402"
R41 R49: library part RSMD040202664, "RES SMD 42.2K OHM 1% 1/10W 0402"
R42 R50 R88: library part RSMD040202616, "RES SMD 4.87K OHM 1% 1/10W 0402"
R44 R114 R117 R134 R136 R137 R141 R142: library part RSMD040202911, "RES SMD 49.9 OHM 1% 1/10W 0402"
R48: library part RSMD040203921, "RES SMD 9.31K OHM 1% 1/10W 0402"
R51 R52 R67 R68 R75 R76 R85 R86 R145 R146 R147 R151 R194: library part RSMD040200001, "RES SMD 0 OHM JUMPER 1/10W 0402"
R53 R69 R77 R87 R90 R112 R113: library part RSMD040200316, "RES 10K OHM 1% 1/10W 0402"
R54 R71 R79: library part OtherRs00006, "RES 0.005 OHM 1% 1/3W 0603"
R55: library part RSMD040203879, "RES SMD 88.7K OHM 1% 1/10W 0402"
R56: library part RSMD040200530, "RES 12K OHM 0.5% 1/10W 0402 SMD"
R57: library part RSMD040200547, "RES SMD 12.4K OHM 1% 1/10W 0402"
R59 R64: library part RSMD040201705, "RES SMD 25.5K OHM 1% 1/10W 0402"
R61 R66: library part RSMD040202910, "RES SMD 49.9K OHM 1% 1/10W 0402"
R62: library part RSMD040200376, "RES SMD 100 OHM 0.5% 1/16W 0402"
R72 R80: library part RSMD040200493, "RES SMD 115K OHM 1% 1/10W 0402"
R73 R81: library part RSMD040203274, "RES SMD 6.65K OHM 1% 1/10W 0402"
R74 R82: library part RSMD040202211, "RES SMD 33K OHM 1% 1/10W 0402"
R84: library part OtherRs00002, "RES SHUNT, 0603, 0.002 OHM, 1%,"
R89: library part RSMD040200983, "RES SMD 17.4K OHM 1% 1/10W 0402"
R115 R121: library part RSMD040201203, "RES SMD 2.2K OHM 1% 1/10W 0402"
R123 R124 R125: library part RSMD040200327, "RES SMD 10 OHM 5% 1/10W 0402"
R126: library part RSMD040200523, "RES SMD 12K OHM 5% 1/10W 0402"
R127 R128 R129: library part RSMD040200306, "RES SMD 10K OHM 5% 1/10W 0402"
R130: library part RSMD040201206, "RES SMD 2.2K OHM 5% 1/10W 0402"
R143: library part RSMD040200354, "RES SMD 100K OHM 5% 1/10W 0402"
R149: library part RSMD040200006, "RES SMD 1K OHM 1% 1/10W 0402"
R150: library part RSMD040202006, "RES SMD 3.6K OHM 1% 1/10W 0402"
R155 R179 R180 R181: library part RSMD040200370, "RES SMD 100 OHM 5% 1/10W 0402"
R191: library part RSMD060311102, "RES SMD 330 OHM 1% 1/10W 0603"
SW1: library part cmp00460, "SWITCH SLIDE SPDT 3A 120V"
SW2 SW4: "Switch Slide SPDT 12V, 500mA"
SW3: library part Switch-2pin, "SWITCH TACTILE SPST-NO 0.05A 24V"
T1 T3 T4 T5: "Signal Conditioning BIAS TEE SURFACE MOUNT"
T2 T6: library part cmp00461, "1:2 MMIC Transformer, 2 - 18 GHz, 50?"
T7 T8: library part cmp00422, "1:2 CORE & WIRE Transformer, 30 - 6000 MHz, 50?"
T9: "1:2 MMIC Transformer, 1.5 - 13 GHz, 50?"
TP1 TP2 TP3: library part cmp00041, "Test Point, Multipurpose, Black, TH"
TP4: library part cmp00040, "Test Point, Multipurpose, Red, TH"
TP5: library part cmp00047, "Test Point, Multipurpose, Brown, TH"
U2: library part cmp00157, "12V, 5A, 30mO eFuse with Adjustable +/-15% Accurate Current Limit, DRC0010J (VSON-10)"
U3 U4: library part cmp00251, "300-mA, 18-V, Ultra-Low IQ, Low-Dropout Linear Voltage Regulator With Power-Good"
U5 U21: library part cmp00171, "Translation - Voltage Levels 4-bit dual-supply bus transceiver with 3-state outputs and independent direction control inputs"
U6 U8: "3-V to 17-V, 2-A/3-A Low-Noise and Low-Ripple Buck Power Module with Integrated Ferrite Bead Filter Compensation"
U7 U40: library part cmp00154, "EEPROM 64K 8KX8 1.8V SER EE IND 1/4AWP RPO"
U9 U14 U16 U19: library part INA2xxAIDGS, "High-Side Measurement, Bi-Directional Current / Power Monitor with I2C Interface, 2.7 to 5.5 V, -40 to 125 degC, 10-pin SOP (DGS10), Green (RoHS & no Sb/Br)"
U10 U15 U17: library part TPS7A9601, "2-A, ultra-low noise ultra-high PSRR RF voltage regulator"
U11 U13: "Low-Noise Positive- and Negative-Output Charge Pump With Integrated LDO"
U12: library part InvBuffer5pin, "Single Bus Inverting Buffer Gate"
U18: "4-V to 18-V Input, 6-A Synchronous SWIFT™ Step-Down Converter with Internally Compensated Advanced Current Mode Control"
U20: library part cmp00175, "Dual-Bit Dual-Supply Bus Transceiver With Configurable Voltage Translation And 3-State Outputs"
U22: library part LMK04828, "Ultra low-noise JESD204B compliant clock jitter cleaner with integrated 2370 to 2630-MHz VCO0"
U23: library part cmp00307, "5-V low-leakage-current, 2: 1, 2-channel precision analog switch"
U24: library part FT4232HL, "USB Interface IC USB HS to Quad UART/ SPI/JTAG/I2C LQFP-6"
U25 U27 U32 U35: "Single Bus Buffer Gate With 3-State Outputs"
U26: library part TMUX1136, "5-V low-leakage-current, 2: 1, 2-channel precision analog switch"
U28: library part cmp00156, "1K Microwire Compatible Serial EEPROM"
U29 U31 U37 U39: library part SN74AxC4T774RSV, "Translation - Voltage Levels 4-bit dual-supply bus transceiver with 3-state outputs and independent direction control inputs"
U30 U36: library part cmp00183, "Low-Voltage 4-Bit 1-of-2 FET Multiplexer/Demultiplexe"
U33: "Single Bus Buffer Gate With 3-State Outputs. Active high enable."
U34: library part SN74LVC1G11DCK, "Single 3-Input Positive-AND Gate"
U38: "Push-pull, supply voltage supervisor with manual reset"
Y1: library part cmp00323, "Crystal, 12 MHz, 18 pF, SMD"
ZZ1: library part cmp00108, "Assembly Notes"

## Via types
v1: diameter 18, hole 8, Top Layer to Bottom Layer, tented both sides, 1558 vias
v2: diameter 20, hole 10, Top Layer to Bottom Layer, tented both sides, 92 vias
v3: diameter 27, hole 15, Top Layer to Bottom Layer, tented both sides, 12 vias

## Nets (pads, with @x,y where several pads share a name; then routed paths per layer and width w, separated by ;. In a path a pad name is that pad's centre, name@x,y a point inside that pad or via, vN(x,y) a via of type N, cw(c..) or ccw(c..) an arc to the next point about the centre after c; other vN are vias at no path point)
0SRX_n: J10.A38 U1.A7 | length 1881.4
  Bottom Layer w6.25: v1(3424.14,1062.51) cw(c3418.71,1067.94) 3418.71,1060.26 3415.73,1060.26 ccw(c3415.73,1053.86) 3411.2,1058.39 ccw(c3415.73,1053.86) 3409.33,1053.86 ccw(c3468.38,1053.86) 3426.62,1012.11 3686.25,752.48 cw(c3608.65,674.87) 3718.4,674.87 3718.4,533.06 ccw(c3788.52,533.06) 3788.52,462.93 4363.31,462.93 4873.97,462.93 ccw(c4873.97,471.77) 4882.81,471.77 J10.A38@4882.81,483.06
0SRX_p: J10.A39 U1.A8 | length 1896.7
  Bottom Layer w6.25: v1(3384.77,1062.51) ccw(c3390.19,1067.94) 3390.19,1060.26 3393.18,1060.26 cw(c3393.18,1053.86) 3397.7,1058.39 cw(c3393.18,1053.86) 3399.58,1053.86 ccw(c3468.38,1053.86) 3419.73,1005.21 3679.36,745.58 cw(c3608.65,674.87) 3708.65,674.87 3708.65,533.06 ccw(c3788.52,533.06) 3788.52,453.18 4873.97,453.18 cw(c4873.97,444.34) 4882.81,444.34 J10.A39@4882.81,433.06
1p0V_DAC: C91.2 C92.2 C93.2 C94.2 L1.2 PP17.1 R84.2 U19.10 | length 76.6
  Bottom Layer w10: v1(1862.6,1934.79) 1878.22,1934.79 1892.79,1920.22 1892.79,1881.08 U19.10@1893.7,1880.18
1SRX_n: J10.B36 U1.B7 | length 1753.5
  Bottom Layer w5: v1(3424.14,1101.88) 3414.81,1101.88 ccw(c3414.81,1096.02) 3408.95,1096.02 ccw(c3416.5,1096.02) 3411.16,1090.69 ccw(c3419.97,1099.49) 3419.97,1087.04 3426.9,1087.04 cw(c3426.9,1065.26) 3448.69,1065.26 3448.69,1045.56
  Bottom Layer w6.25: 3448.87,1045.37 ccw(c3462.65,1045.37) 3452.91,1035.63 3740.15,748.39 cw(c3662.55,670.78) 3772.3,670.78 3772.3,630.34 ccw(c3839.7,630.34) 3773.25,619.03 ccw(c3779.41,620.08) 3773.29,618.85 ccw(c3842.67,633.3) 3828.22,563.92 ccw(c3829.45,570.05) 3828.37,563.89 ccw(c3839.7,630.34) 3839.7,562.93 3853.31,562.93 4823.97,562.93 ccw(c4823.97,571.77) 4832.81,571.77 J10.B36@4832.81,583.06
1SRX_p: J10.B37 U1.B8 | length 1766.9
  Bottom Layer w5: v1(3384.77,1101.88) 3394.09,1101.88 cw(c3394.09,1096.02) 3399.95,1096.02 3399.95,1095.97 ccw(c3416.36,1095.97) 3404.76,1084.36 ; 3404.86,1084.26 ccw(c3419.88,1099.28) 3419.88,1078.04 3424.06,1078.04 cw(c3424.06,1062.41) 3439.69,1062.41 3439.69,1045.52
  Bottom Layer w6.25: 3439.12,1045.41 ccw(c3462.75,1045.41) 3446.04,1028.71 3733.26,741.49 cw(c3662.55,670.78) 3762.55,670.78 3762.55,633.3 ccw(c3842.67,633.3) 3842.67,553.18 4823.97,553.18 cw(c4823.97,544.34) 4832.81,544.34 J10.B37@4832.81,533.06
2p3V_Analog_LDO: C40.2 C47.2 C50.2 FC3.3 R70.2 U10.1 U10.2 U15.1 U15.2 U17.1 U17.2 | length 20
  Top Layer w10: v1(938.37,947.83) U17.1@958.37,947.83
2SRX_n: J10.B32 U1.A4 | length 1477.8
  Bottom Layer w6.25: v1(3542.25,1062.51) cw(c3536.82,1067.94) 3536.82,1060.26 3533.84,1060.26 ccw(c3533.84,1053.86) 3529.31,1058.39 ccw(c3533.84,1053.86) 3527.44,1053.86 3527.44,1052.39 ccw(c3627.44,1052.39) 3556.73,981.68 3746.19,792.22 ccw(c3816.9,862.93) 3816.9,762.93 4823.97,762.93 ccw(c4823.97,771.77) 4832.81,771.77 J10.B32@4832.81,783.06
2SRX_p: J10.B33 U1.A5 | length 1493.1
  Bottom Layer w6.25: v1(3502.88,1062.51) ccw(c3508.31,1067.94) 3508.31,1060.26 3511.29,1060.26 cw(c3511.29,1053.86) 3515.81,1058.39 cw(c3511.29,1053.86) 3517.69,1053.86 3517.69,1052.39 ccw(c3627.44,1052.39) 3549.83,974.78 3739.29,785.33 ccw(c3816.9,862.93) 3816.9,753.18 4823.97,753.18 cw(c4823.97,744.34) 4832.81,744.34 J10.B33@4832.81,733.06
3p3_FMC: J10.C39 J10.D36 J10.D38 J10.D40 J10.Z40 | length 480.2
  Top Layer w12.1: v1(4732.81,583.06) 4760.55,555.32 4760.55,510.79 v1(4732.81,483.06) 4713.76,464.01 4713.76,402.11 v1(4732.81,383.06) v1(4782.81,433.06) 4805.87,410 4905.87,410 v1(4932.81,383.06)
3p3V_Clock: C26.2 C56.2 C57.2 C64.2 C65.2 C115.2 C116.2 C117.2 C118.2 C119.2 C120.2 C121.2 C122.2 C123.2 C124.2 C125.2 C126.2 FB1.2 PP3.1 R39.2 R182.1 U11.3 U13.3 U22.10 U22.17 U22.21 U22.26 U22.33 U22.36 U22.39 U22.42 U22.45 U22.47 U22.53 U22.64 | length 817.1
  Top Layer w10: v1(2168.25,1898.8) U22.47@2203.25,1898.8 ; v1(2168.25,1938.17) U22.45@2203.25,1938.17 ; v1(2168.25,1997.22) U22.42@2203.25,1997.22 ; U22.64@2524.11,1853.52 2524.11,1825.41 2529.03,1820.49 v1(2529.03,1818.52) ; U22.17@2524.11,2199.98 v1(2524.11,2234.98) ; U22.10@2549.7,2056.28 2563.93,2056.28 2567.25,2052.96 2578.84,2052.96 2584.7,2047.1 v1(2584.7,2021.28)
  Bottom Layer w8: v1(919.76,2461.63) 993.63,2461.63 1045.16,2513.15 v1(1473.83,2513.15)
  other v1: 1249.34,1588.73 1269.34,1588.73 1289.34,1588.73 1249.34,1608.73 1269.34,1608.73 1289.34,1608.73 1423.96,1713.71 1443.96,1713.71 1463.96,1713.71 1423.96,1733.71 1443.96,1733.71 1463.96,1733.71 2307.58,1865.33 2203.25,2056.28 2203.25,2115.33 2203.25,2174.39 2346.95,2199.98 2445.37,2199.98 2737.31,2271.79 1476.41,2440.59 1496.41,2440.59 1476.41,2460.59 1496.41,2460.59 1476.41,2480.59 1496.41,2480.59
3p3V_EEPROM: C73.1 C245.2 D4.3 U23.8@4702.69,247.98 U40.8
  other v1: 4810.97,106.08 4702.69,179.01 4825.24,209.51 4702.69,247.98
3p3V_Utility: C13.2 C42.1 C55.1 C68.2 C69.2 C72.1 C80.1 C95.1 C97.2 C148.2 C149.2 C150.2 C151.2 C152.2 C155.1 C158.2 C161.1 C163.2 C167.1 C168.1 D4.2 FB7.1 FB8.1 R29.2 R45.2 R46.2 R53.2 R58.2 R67.1 R76.1 R85.1 R86.1 R111.1 R115.1 R116.1 R118.2 R119.2 R121.1 R122.1 R123.2 R127.2 R128.2 R129.2 R131.1 R132.1 R133.2 R135.1 R138.1 R139.1 R157.1 R170.1 R191.2 U3.1 U5.6 U5.14 U5.15 U5.16 U7.8 U9.6 U12.5 U14.6 U16.6 U19.6 U21.6 U21.14 U21.15 U21.16 U24.20 U24.31 U24.42 U24.50 U24.56 U25.5 U26.8@797.38,2153.25 U27.5 U28.8 U29.13 U30.16 U33.5 U36.16 U37.6 U37.14 U37.15 U37.16 | length 630.6
  Top Layer w8: v1(507.29,1616.44) U36.16@507.29,1647.44 ; U5.6@907.36,1812.47 932.95,1812.47 939.03,1806.39 v1(941.73,1806.39)
  Top Layer w12: v1(559.06,1975.99) U24.20@559.06,1935.99 559.06,1890.99 v1(564.06,1890.99) ; U24.56@657.49,2374.97 v1(657.49,2429.97) ; v1(775.6,1895.99) U24.31@775.6,1935.99 v1(775.6,1975.99) ; U24.50@775.6,2374.97 v1(775.6,2429.97) ; U24.42@867.13,2185.01 907.1,2185.01 v1(917.13,2195.01) ; R67.1@1314.45,823.96 1343.82,823.96 v1(1344.45,824.59)
  Top Layer w18: R115.1@662.86,1826.62 v1(696.86,1826.62) ; R139.1@1195.09,2156.71 1195.09,2124.21 v1(1197.46,2121.83) ; R157.1@1195.09,2216.71 1195.93,2215.87 1201.49,2215.87 v1(1215.41,2201.95)
  Bottom Layer w8: v1(507.29,1616.44) 507.29,1619.14 510.45,1622.3 510.45,1627.02 C167.1@516.29,1632.86 ; U37.6@558.19,1794.29 v1(583.19,1794.29) ; U21.6@1209.34,2236.32 1209.34,2210.73 1215.41,2204.65 v1(1215.41,2201.95)
  Bottom Layer w12: R76.1@1166.34,1017.82 v1(1166.34,1037.82)
  other v1: 4241.78,56.2 4195.01,111.32 4889.71,143.48 1344.42,574.59 821.87,1052.32 1247.95,1094.56 798.05,1422.88 958.05,1422.88 472.57,1454.17 1003.95,1457.01 1139.34,1460.42 927.57,1481.29 262.43,1508.65 262.43,1528.65 262.43,1548.65 448.71,1784.42 491.45,1787.79 448.71,1804.17 1036.09,1812.47 247.33,1826.62 2002.44,1880.18 872.24,1983.65 982.24,1995.46 1037.24,1995.46 1115.72,2017.34 330.16,2043.55 487.77,2047.21 1839.63,2054.58 691.13,2068.86 721.13,2068.86 299.53,2078.55 1046.4,2113.2 1219.21,2121.83 797.38,2153.25 1931.2,2156.98 691.13,2158.88 725.13,2158.88 1558.34,2201.21 298.16,2283.43 1046.4,2283.43 1195.09,2286.71 667.81,2325.17 1404.09,2334.95 519.69,2464.34 554.38,2464.34
3P3VAUX-FMC: D4.1 J10.D32 R95.2 U23.1 U23.5 | length 254.8
  Top Layer w5: U23.5@4669.81,208.61 v1(4669.81,179.01) 4633.43,179.01 4598.65,213.79 4598.65,278.73 4607.27,287.35 U23.1@4669.81,287.35
  other v1: 4889.71,68.68 4732.81,783.06
3SRX_n: J10.A34 U1.B4 | length 1698.8
  Bottom Layer w5: v1(3542.25,1101.88) 3532.92,1101.88 ccw(c3532.92,1096.02) 3527.06,1096.02 ccw(c3534.61,1096.02) 3529.27,1090.69 ccw(c3538.08,1099.49) 3538.08,1087.04 3545.01,1087.04 cw(c3545.01,1065.26) 3566.8,1065.26 3566.8,1045.56
  Bottom Layer w6.25: 3566.8,1045.56 cw(c3564.99,1043.75) 3567.36,1044.71 cw(c3564.99,1043.75) 3567.55,1043.75 3567.55,1036.05 ; 3567.55,1036.01 ccw(c3573.8,1036.21) 3567.64,1035.13 ccw(c3601.91,1041.52) 3568.09,1033.06 ccw(c3601.91,1041.52) 3573.09,1021.91 ccw(c3578.27,1025.4) 3573.74,1021.1 3652.48,942.35 ccw(c3723.19,1013.07) 3723.19,913.07 4433.1,913.07 cw(c4433.1,883.28) 4462.89,883.28 4462.89,832.08 ccw(c4482.01,832.08) 4482.01,812.95 4833.5,812.95 cw(c4833.5,783.76) 4862.69,783.76 4862.69,674.21 ccw(c4873.97,674.21) 4873.97,662.93 ccw(c4873.97,671.77) 4882.81,671.77 J10.A34@4882.81,683.06
3SRX_p: J10.A35 U1.B5 | length 1712.2
  Bottom Layer w5: v1(3502.88,1101.88) 3512.2,1101.88 cw(c3512.2,1096.02) 3518.06,1096.02 3518.06,1095.97 ccw(c3534.47,1095.97) 3522.87,1084.36 ; 3522.97,1084.26 ccw(c3537.99,1099.28) 3537.99,1078.04 3542.17,1078.04 cw(c3542.17,1062.41) 3557.8,1062.41 3557.8,1045.52
  Bottom Layer w6.25: 3557.55,1045.52 ccw(c3566.8,1045.56) 3557.7,1043.88 cw(c3551.55,1042.78) 3557.8,1042.82 3557.8,1041.52 ccw(c3601.91,1041.52) 3558.62,1033.06 ccw(c3601.91,1041.52) 3570.72,1010.33 3645.59,935.46 ccw(c3723.19,1013.07) 3723.19,903.32 4433.1,903.32 cw(c4433.1,883.28) 4453.14,883.28 4453.14,832.08 ccw(c4482.01,832.08) 4482.01,803.2 4833.5,803.2 cw(c4833.5,783.76) 4852.94,783.76 4852.94,674.21 ccw(c4873.97,674.21) 4873.97,653.18 cw(c4873.97,644.34) 4882.81,644.34 J10.A35@4882.81,633.06
4SRX_n: J10.Y30 U1.D1 | length 1514.9
  Top Layer w6.25: U1.D1@3660.36,1180.62 ccw(c3675.17,1180.62) 3675.17,1165.81 4236.23,1165.81 ; 4236.23,1166.31 4236.23,1165.81 ; v1(4982.81,883.06) 4982.81,868.01 cw(c4977.73,868.01) 4977.73,862.93 4897.29,862.93 cw(c4897.29,877.41) 4882.81,877.41 ccw(c4843.76,877.41) 4843.76,916.47 4673.15,916.47 cw(c4673.15,937.2) 4652.41,937.2 ccw(c4626.38,937.2) 4626.38,963.23 4444.62,963.23 cw(c4444.62,1063.23) 4373.91,992.52 4335.18,1031.25 cw(c4395.96,1092.04) 4310,1092.04 ccw(c4236.23,1092.04) 4236.23,1165.81
4SRX_p: J10.Y31 U1.C1 | length 1514.4
  Top Layer w6.25: U1.C1@3660.36,1141.25 cw(c3675.17,1141.25) 3675.17,1156.06 4236.23,1156.06 cw(c4236.23,1092.04) 4300.25,1092.04 ccw(c4395.96,1092.04) 4328.28,1024.36 4367.02,985.63 ccw(c4444.62,1063.23) 4444.62,953.48 4626.38,953.48 cw(c4626.38,937.2) 4642.66,937.2 ccw(c4673.15,937.2) 4673.15,906.72 4843.76,906.72 cw(c4843.76,877.41) 4873.06,877.41 ccw(c4897.29,877.41) 4897.29,853.18 4977.73,853.18 cw(c4977.73,848.1) 4982.81,848.1 v1(4982.81,833.06)
5SRX_n: J10.A30 U1.D2 | length 1512.3
  Bottom Layer w6.25: v1(3620.99,1180.62) cw(c3615.56,1175.19) 3623.24,1175.19 3623.24,1172.21 ccw(c3629.64,1172.21) 3625.11,1167.69 ccw(c3629.64,1172.21) 3629.64,1165.81 3780.79,1165.81 cw(c3780.79,1140.7) 3805.9,1140.7 ccw(c3833.48,1140.7) 3829.48,1113.41 3829.77,1113.12 4334.73,1113.12 cw(c4334.73,1085.32) 4362.53,1085.32 4362.53,984.23 ccw(c4383.52,984.23) 4383.52,963.23 4586.2,963.23 cw(c4586.2,936.47) 4612.97,936.47 4612.97,931.55 ccw(c4631.89,931.55) 4631.89,912.63 4788.89,912.63 cw(c4788.89,888.86) 4812.66,888.86 4812.66,876.61 ccw(c4826.34,876.61) 4826.34,862.93 4873.97,862.93 ccw(c4873.97,871.77) 4882.81,871.77 J10.A30@4882.81,883.06
5SRX_p: J10.A31 U1.C2 | length 1516.6
  Bottom Layer w6.25: v1(3620.99,1141.25) ccw(c3615.56,1146.68) 3623.24,1146.68 3623.24,1149.66 cw(c3629.64,1149.66) 3625.11,1154.19 cw(c3629.64,1149.66) 3629.64,1156.06 3780.79,1156.06 cw(c3780.79,1140.7) 3796.15,1140.7 ccw(c3833.48,1140.7) 3833.48,1103.37 ; 3829.44,1103.37 3833.48,1103.37 ; J10.A31@4882.81,833.06 4882.81,844.34 ccw(c4873.97,844.34) 4873.97,853.18 4826.34,853.18 cw(c4826.34,876.61) 4802.91,876.61 4802.91,888.86 ccw(c4788.89,888.86) 4788.89,902.88 4631.89,902.88 cw(c4631.89,931.55) 4603.22,931.55 4603.22,940.5 ccw(c4597.05,939.52) 4603.07,941.19 ccw(c4586.2,936.47) 4590.92,953.33 ccw(c4589.26,947.31) 4590.24,953.48 4384.28,953.48 cw(c4384.28,984.99) 4352.78,984.99 4352.78,1085.32 ccw(c4334.73,1085.32) 4334.73,1103.37 3833.48,1103.37
5V_Utility: C15.2 R25.2 R31.2 U4.1
  other v1: 262.43,1158.65 262.43,1178.65 262.43,1198.65
6SRX_n: J10.Z28 U1.G1 | length 1492.5
  Top Layer w6.25: U1.G1@3660.36,1298.73 ccw(c3675.17,1298.73) 3675.17,1283.92 3698.74,1283.92 4317.25,1283.92 ccw(c4317.25,1316.01) 4339.94,1293.31 ; 4339.94,1293.32 4342.94,1296.32 cw(c4389.11,1250.15) 4389.11,1315.44 4413.4,1315.44 cw(c4413.4,1205.69) 4491,1283.3 4614.93,1159.37 cw(c4541.22,1085.66) 4645.46,1085.66 ccw(c4696.71,1085.66) 4660.47,1049.42 4691.12,1018.77 cw(c4661.98,989.63) 4703.19,989.63 ccw(c4729.89,989.63) 4729.89,962.93 4927.73,962.93 ccw(c4927.73,968.01) 4932.81,968.01 v1(4932.81,983.06)
6SRX_p: J10.Z29 U1.F1 | length 1492.5
  Top Layer w6.25: U1.F1@3660.36,1259.36 cw(c3675.17,1259.36) 3675.17,1274.17 4317.25,1274.17 ccw(c4317.25,1316.01) 4346.84,1286.43 4349.83,1289.42 cw(c4389.11,1250.15) 4389.11,1305.69 4413.4,1305.69 cw(c4413.4,1205.69) 4484.11,1276.4 4608.04,1152.47 cw(c4541.22,1085.66) 4635.71,1085.66 ccw(c4696.71,1085.66) 4653.58,1042.53 4684.23,1011.88 cw(c4661.98,989.63) 4693.44,989.63 ccw(c4729.89,989.63) 4729.89,953.18 4927.73,953.18 cw(c4927.73,948.1) 4932.81,948.1 v1(4932.81,933.06)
